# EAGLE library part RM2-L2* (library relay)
4 GHz 2 FORM C MICROWAVE RELAY NAiS Source: http://www.mew-europe.com/.. en_ds_61305_0000.pdf
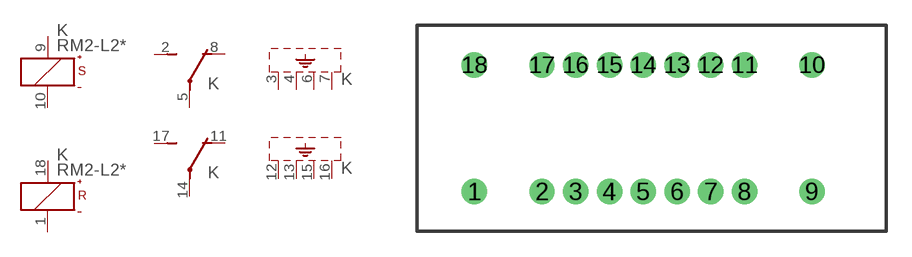
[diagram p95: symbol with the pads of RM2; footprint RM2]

Designator prefix K; gates S=K+-S R=K+-R 1=U 2=U S1=SHIELD-4 S2=SHIELD-4

## RM2-L2-3V (OC_FARNELL: unknown; OC_NEWARK: unknown), RM2-L2-4.5V (OC_FARNELL: unknown; OC_NEWARK: unknown), RM2-L2-6V (OC_FARNELL: unknown; OC_NEWARK: unknown), RM2-L2-9V (OC_FARNELL: unknown; OC_NEWARK: unknown), RM2-L2-12V (OC_FARNELL: unknown; OC_NEWARK: unknown), RM2-L2-24V (OC_FARNELL: unknown; OC_NEWARK: unknown)  [RM2]
1  R:-  pas
2  1:S  pas
3  S1:SH  pas
4  S1:SH  pas
5  1:P  pas
6  S1:SH  pas
7  S1:SH  pas
8  1:O  pas
9  S:+  pas
10  S:-  pas
11  2:O  pas
12  S2:SH  pas
13  S2:SH  pas
14  2:P  pas
15  S2:SH  pas
16  S2:SH  pas
17  2:S  pas
18  R:+  pas

## Footprint RM2 (pad centres in mm)
4 GHz 2 FORM C MICROWAVE RELAY NAiS Source: http://www.mew-europe.com/.. en_ds_61305_0000.pdf
drill 1 round: 1 -10,-3.75; 2 -6,-3.75; 3 -4,-3.75; 4 -2,-3.75; 5 0,-3.75; 6 2,-3.75; 7 4,-3.75; 8 6,-3.75; 9 10,-3.75; 10 10,3.75; 11 6,3.75; 12 4,3.75; 13 2,3.75; 14 0,3.75; 15 -2,3.75; 16 -4,3.75; 17 -6,3.75; 18 -10,3.75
